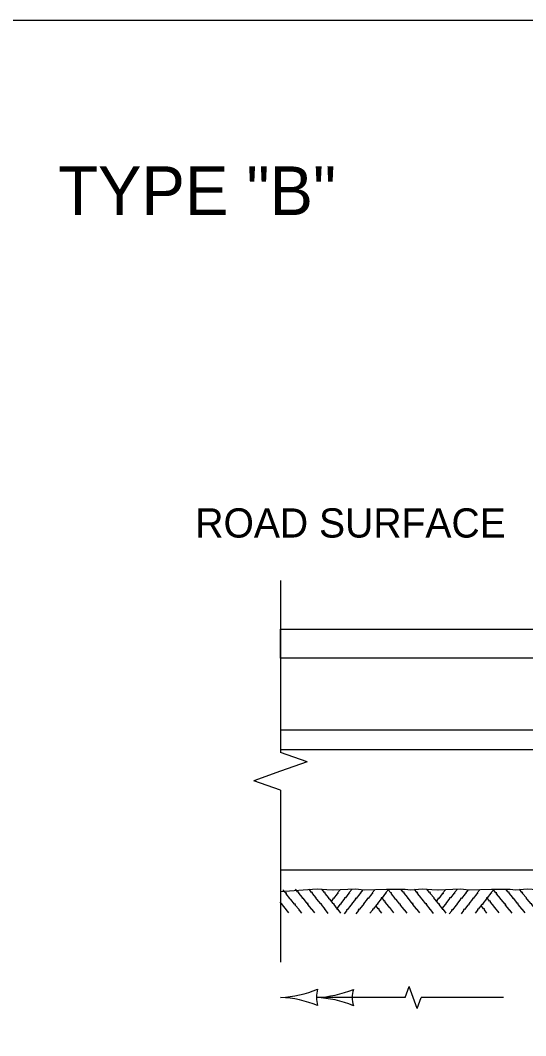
# Model space of a CAD drawing. Extents: x 49991.4 to 50022.1, y 49985 to 50011.4.
# Drawn here: x 50012.115 to 50013.153, y 49996.914 to 49998.999 of the extents above; entities that cross this region are included whole.
import ezdxf

# ---------------------------------------------------------------- set-up
doc = ezdxf.new("R2010")
doc.units = 0
for name, color, linetype in [('Level 1', 7, 'Continuous'), ('Level 2', 7, 'Continuous'), ('Level 3', 7, 'Continuous'), ('Level 4', 7, 'Continuous'), ('Level 6', 7, 'Continuous')]:
    doc.layers.add(name, color=color, linetype=linetype)

msp = doc.modelspace()

# ---------------------------------------------------------------- linework, layer by layer
at = {"layer": 'Level 1'}
for p, q in [((50012.6491, 49997.6892), (50012.6493, 49997.7486)), ((50012.6493, 49997.7486), (50013.8245, 49997.7486)), ((50014.1009, 49997.6892), (50012.6491, 49997.6892)), ((50012.6493, 49997.5423), (50014.7997, 49997.5423))]:
    msp.add_line(p, q, dxfattribs=at)
msp.add_lwpolyline([(49999.3835, 49998.9992), (50016.7501, 49998.9992), (50016.7501, 49987.7988), (49999.3835, 49987.7988)], close=True, dxfattribs=at)
for points in [[(50012.6482, 49997.21), (50012.7245, 49997.2154), (50012.7439, 49997.2142), (50012.7585, 49997.2135)], [(50012.6931, 49997.1653), (50012.6883, 49997.1716), (50012.6867, 49997.1713), (50012.6871, 49997.1727), (50012.6794, 49997.1819), (50012.6799, 49997.1839), (50012.6781, 49997.1841), (50012.6704, 49997.1937), (50012.6687, 49997.1941), (50012.6685, 49997.1959), (50012.6609, 49997.2051), (50012.6613, 49997.207), (50012.6595, 49997.207), (50012.6542, 49997.2135)], [(50012.7195, 49997.1659), (50012.7139, 49997.1731), (50012.7124, 49997.1728), (50012.7127, 49997.1741), (50012.7051, 49997.1835), (50012.7057, 49997.1854), (50012.7037, 49997.1855), (50012.6961, 49997.1953), (50012.6944, 49997.1956), (50012.6943, 49997.1974), (50012.6867, 49997.2065), (50012.6869, 49997.2085), (50012.6849, 49997.2085), (50012.6799, 49997.2149)], [(50012.7473, 49997.1651), (50012.7418, 49997.1725), (50012.7403, 49997.1721), (50012.7405, 49997.1734), (50012.7333, 49997.183), (50012.7335, 49997.1847), (50012.7317, 49997.1849), (50012.7239, 49997.1945), (50012.7223, 49997.195), (50012.7221, 49997.1967), (50012.7147, 49997.2059), (50012.7148, 49997.2076), (50012.7129, 49997.2076), (50012.7079, 49997.2145)], [(50012.7574, 49997.1855), (50012.7502, 49997.1945), (50012.7485, 49997.1951), (50012.7484, 49997.1968), (50012.7407, 49997.2059), (50012.7411, 49997.2079), (50012.7393, 49997.2079), (50012.7337, 49997.2148)], [(50012.7559, 49997.2135), (50012.8029, 49997.2154), (50012.8207, 49997.2133), (50012.8665, 49997.2148), (50012.9049, 49997.2151), (50012.9157, 49997.2136), (50012.9405, 49997.2154), (50012.9597, 49997.2142), (50012.9745, 49997.2135)], [(50012.7723, 49997.2141), (50012.7663, 49997.207), (50012.7669, 49997.2055), (50012.7653, 49997.2055), (50012.7581, 49997.1959), (50012.7573, 49997.1959)], [(50012.7964, 49997.2149), (50012.7904, 49997.2079), (50012.7911, 49997.2065), (50012.7897, 49997.2065), (50012.7823, 49997.1969), (50012.7802, 49997.1969), (50012.7807, 49997.1953), (50012.7729, 49997.1855), (50012.7729, 49997.1839), (50012.7712, 49997.1833), (50012.7651, 49997.1755)], [(50012.8183, 49997.2133), (50012.8127, 49997.2065), (50012.8133, 49997.2052), (50012.8119, 49997.2052), (50012.8047, 49997.1956), (50012.8027, 49997.1956), (50012.8029, 49997.1939), (50012.7952, 49997.1842), (50012.7952, 49997.1825), (50012.7935, 49997.1818), (50012.7862, 49997.1725), (50012.7845, 49997.1722), (50012.7849, 49997.1705), (50012.7795, 49997.1639)], [(50012.8432, 49997.2141), (50012.8371, 49997.207), (50012.8378, 49997.2055), (50012.8365, 49997.2055), (50012.8289, 49997.1959), (50012.8271, 49997.1959), (50012.8273, 49997.1941), (50012.8197, 49997.1847), (50012.8197, 49997.1827), (50012.8179, 49997.1821), (50012.8107, 49997.1727), (50012.8089, 49997.1727), (50012.8093, 49997.1707), (50012.8041, 49997.1644)], [(50012.8717, 49997.2149), (50012.8657, 49997.2076), (50012.8665, 49997.2064), (50012.8649, 49997.2064), (50012.8577, 49997.1968), (50012.8558, 49997.1968), (50012.8559, 49997.1951), (50012.8483, 49997.1855), (50012.8483, 49997.1836), (50012.8467, 49997.1831), (50012.8393, 49997.1737), (50012.8377, 49997.1735), (50012.8379, 49997.1716), (50012.8325, 49997.1653)], [(50012.9091, 49997.1653), (50012.9043, 49997.1716), (50012.9027, 49997.1713), (50012.9029, 49997.1727), (50012.8954, 49997.1819), (50012.8957, 49997.1839), (50012.8941, 49997.1841), (50012.8864, 49997.1937), (50012.8847, 49997.1941), (50012.8845, 49997.1959), (50012.8769, 49997.2051), (50012.8773, 49997.207), (50012.8753, 49997.207), (50012.8702, 49997.2135)], [(50012.9355, 49997.1659), (50012.9299, 49997.1731), (50012.9284, 49997.1728), (50012.9285, 49997.1741), (50012.9211, 49997.1835), (50012.9213, 49997.1854), (50012.9197, 49997.1855), (50012.9121, 49997.1953), (50012.9104, 49997.1956), (50012.9103, 49997.1974), (50012.9027, 49997.2065), (50012.9029, 49997.2085), (50012.9009, 49997.2085), (50012.8959, 49997.2149)], [(50012.9633, 49997.1651), (50012.9578, 49997.1725), (50012.9563, 49997.1721), (50012.9565, 49997.1734), (50012.9489, 49997.183), (50012.9494, 49997.1847), (50012.9477, 49997.1849), (50012.9399, 49997.1945), (50012.9383, 49997.195), (50012.9381, 49997.1967), (50012.9307, 49997.2059), (50012.9308, 49997.2076), (50012.9289, 49997.2076), (50012.9239, 49997.2145)], [(50012.9734, 49997.1855), (50012.9662, 49997.1945), (50012.9644, 49997.1951), (50012.9643, 49997.1968), (50012.9567, 49997.2059), (50012.9569, 49997.2079), (50012.9549, 49997.2079), (50012.9497, 49997.2148)], [(50012.9719, 49997.2135), (50013.0189, 49997.2154), (50013.0367, 49997.2133), (50013.0825, 49997.2148), (50013.1209, 49997.2151), (50013.1313, 49997.2136), (50013.1564, 49997.2154), (50013.1757, 49997.2142), (50013.1905, 49997.2135)], [(50012.9883, 49997.2141), (50012.9823, 49997.207), (50012.9829, 49997.2055), (50012.9813, 49997.2055), (50012.9741, 49997.1959), (50012.9733, 49997.1959)], [(50013.0123, 49997.2149), (50013.0064, 49997.2079), (50013.0069, 49997.2065), (50013.0057, 49997.2065), (50012.9981, 49997.1969), (50012.9962, 49997.1969), (50012.9963, 49997.1953), (50012.9887, 49997.1855), (50012.9887, 49997.1839), (50012.9871, 49997.1833), (50012.9811, 49997.1755)], [(50013.0343, 49997.2133), (50013.0289, 49997.2065), (50013.0293, 49997.2052), (50013.0281, 49997.2052), (50013.0207, 49997.1956), (50013.0187, 49997.1956), (50013.0189, 49997.1939), (50013.0112, 49997.1842), (50013.0112, 49997.1825), (50013.0095, 49997.1818), (50013.0022, 49997.1725), (50013.0004, 49997.1722), (50013.0007, 49997.1705), (50012.9955, 49997.1639)], [(50013.0592, 49997.2141), (50013.0531, 49997.207), (50013.0538, 49997.2055), (50013.0525, 49997.2055), (50013.0449, 49997.1959), (50013.0431, 49997.1959), (50013.0433, 49997.1941), (50013.0357, 49997.1847), (50013.0357, 49997.1827), (50013.0339, 49997.1821), (50013.0267, 49997.1727), (50013.0249, 49997.1727), (50013.0251, 49997.1707), (50013.0199, 49997.1644)], [(50013.0877, 49997.2149), (50013.0817, 49997.2076), (50013.0825, 49997.2064), (50013.0809, 49997.2064), (50013.0737, 49997.1968), (50013.0718, 49997.1968), (50013.0719, 49997.1951), (50013.0643, 49997.1855), (50013.0643, 49997.1836), (50013.0627, 49997.1831), (50013.0553, 49997.1737), (50013.0533, 49997.1735), (50013.0538, 49997.1716), (50013.0485, 49997.1653)], [(50013.1251, 49997.1653), (50013.1203, 49997.1716), (50013.1187, 49997.1713), (50013.1189, 49997.1727), (50013.1114, 49997.1819), (50013.1117, 49997.1839), (50013.1101, 49997.1841), (50013.1024, 49997.1937), (50013.1007, 49997.1941), (50013.1005, 49997.1959), (50013.0928, 49997.2051), (50013.0933, 49997.207), (50013.0913, 49997.207), (50013.0862, 49997.2135)], [(50013.1513, 49997.1659), (50013.1459, 49997.1731), (50013.1444, 49997.1728), (50013.1445, 49997.1741), (50013.1371, 49997.1835), (50013.1373, 49997.1854), (50013.1357, 49997.1855), (50013.1281, 49997.1953), (50013.1264, 49997.1956), (50013.1263, 49997.1974), (50013.1185, 49997.2065), (50013.1189, 49997.2085), (50013.1169, 49997.2085), (50013.1119, 49997.2149)], [(50013.1792, 49997.1651), (50013.1738, 49997.1725), (50013.1721, 49997.1721), (50013.1725, 49997.1734), (50013.1649, 49997.183), (50013.1654, 49997.1847), (50013.1637, 49997.1849), (50013.1559, 49997.1945), (50013.1543, 49997.195), (50013.1541, 49997.1967), (50013.1463, 49997.2059), (50013.1468, 49997.2076), (50013.1449, 49997.2076), (50013.1399, 49997.2145)], [(50012.7573, 49997.1959), (50012.7562, 49997.1959), (50012.7563, 49997.1941), (50012.7537, 49997.1907)], [(50012.8821, 49997.1661), (50012.8733, 49997.1771), (50012.8717, 49997.1775), (50012.8715, 49997.1791), (50012.8641, 49997.1884), (50012.8642, 49997.1902), (50012.8624, 49997.1902), (50012.8575, 49997.1968)], [(50012.9733, 49997.1959), (50012.9722, 49997.1959), (50012.9723, 49997.1941), (50012.9697, 49997.1907)], [(50013.0981, 49997.1661), (50013.0893, 49997.1771), (50013.0877, 49997.1775), (50013.0875, 49997.1791), (50013.0801, 49997.1884), (50013.0802, 49997.1902), (50013.0784, 49997.1902), (50013.0733, 49997.1968)], [(50012.6661, 49997.1661), (50012.6482, 49997.1885)], [(50012.7731, 49997.1653), (50012.7677, 49997.1727), (50012.7663, 49997.1722), (50012.7664, 49997.1735), (50012.7591, 49997.183), (50012.7593, 49997.1848), (50012.7575, 49997.1849), (50012.7569, 49997.1855)], [(50012.8569, 49997.1656), (50012.8517, 49997.1722), (50012.8519, 49997.1741), (50012.8499, 49997.1741), (50012.8449, 49997.1809)], [(50012.9891, 49997.1653), (50012.9837, 49997.1727), (50012.9823, 49997.1722), (50012.9825, 49997.1735), (50012.9749, 49997.183), (50012.9753, 49997.1848), (50012.9735, 49997.1849), (50012.9733, 49997.1855)], [(50013.0729, 49997.1656), (50013.0677, 49997.1722), (50013.0679, 49997.1741), (50013.0659, 49997.1741), (50013.0609, 49997.1809)]]:
    msp.add_lwpolyline(points, dxfattribs=at)
at = {"layer": 'Level 3'}
for p, q in [((50012.9052, 49996.9922), (50012.9133, 49997.015)), ((50012.9214, 49996.9922), (50012.9133, 49997.015)), ((50012.9052, 49996.9922), (50012.7227, 49996.9922)), ((50012.9295, 49996.9694), (50012.9214, 49996.9922)), ((50012.9295, 49996.9694), (50012.9376, 49996.9922)), ((50013.1072, 49996.9922), (50012.9376, 49996.9922))]:
    msp.add_line(p, q, dxfattribs=at)
for centre, radius, start, end in [((50012.6378, 49997.2252), 0.233, 272.8273, 292.0772), ((50012.7775, 49996.9925), 0.0548, 162.1388, 197.8612), ((50012.7112, 49997.2249), 0.233, 272.8273, 292.0772), ((50012.8509, 49996.9922), 0.0548, 162.1388, 197.8612), ((50012.6401, 49996.7703), 0.2223, 67.456, 87.6395), ((50012.7136, 49996.7701), 0.2223, 67.456, 87.6395)]:
    msp.add_arc(centre, radius, start, end, dxfattribs=at)
at = {"layer": 'Level 4'}
for p, q in [((50012.6493, 49997.5013), (50014.8057, 49997.5013)), ((50012.6493, 49997.2547), (50015.1696, 49997.2547))]:
    msp.add_line(p, q, dxfattribs=at)
at = {"layer": 'Level 6'}
for p, q in [((50012.6491, 49997.8486), (50012.6491, 49997.4957)), ((50012.7039, 49997.4762), (50012.6491, 49997.4957)), ((50012.7039, 49997.4762), (50012.6491, 49997.4568)), ((50012.6491, 49997.4568), (50012.5943, 49997.4374)), ((50012.6491, 49997.4179), (50012.5943, 49997.4374)), ((50012.6491, 49997.4179), (50012.6491, 49997.0651))]:
    msp.add_line(p, q, dxfattribs=at)

# ---------------------------------------------------------------- texts
at = {"layer": 'Level 2'}
for s, height, p in [('TYPE "B"', 0.1, (50012.1927, 49998.5992)), ('ROAD SURFACE', 0.06, (50012.4741, 49997.9369))]:
    msp.add_text(s, height=height, dxfattribs=at).set_placement(p)

doc.saveas('drawing.dxf')
